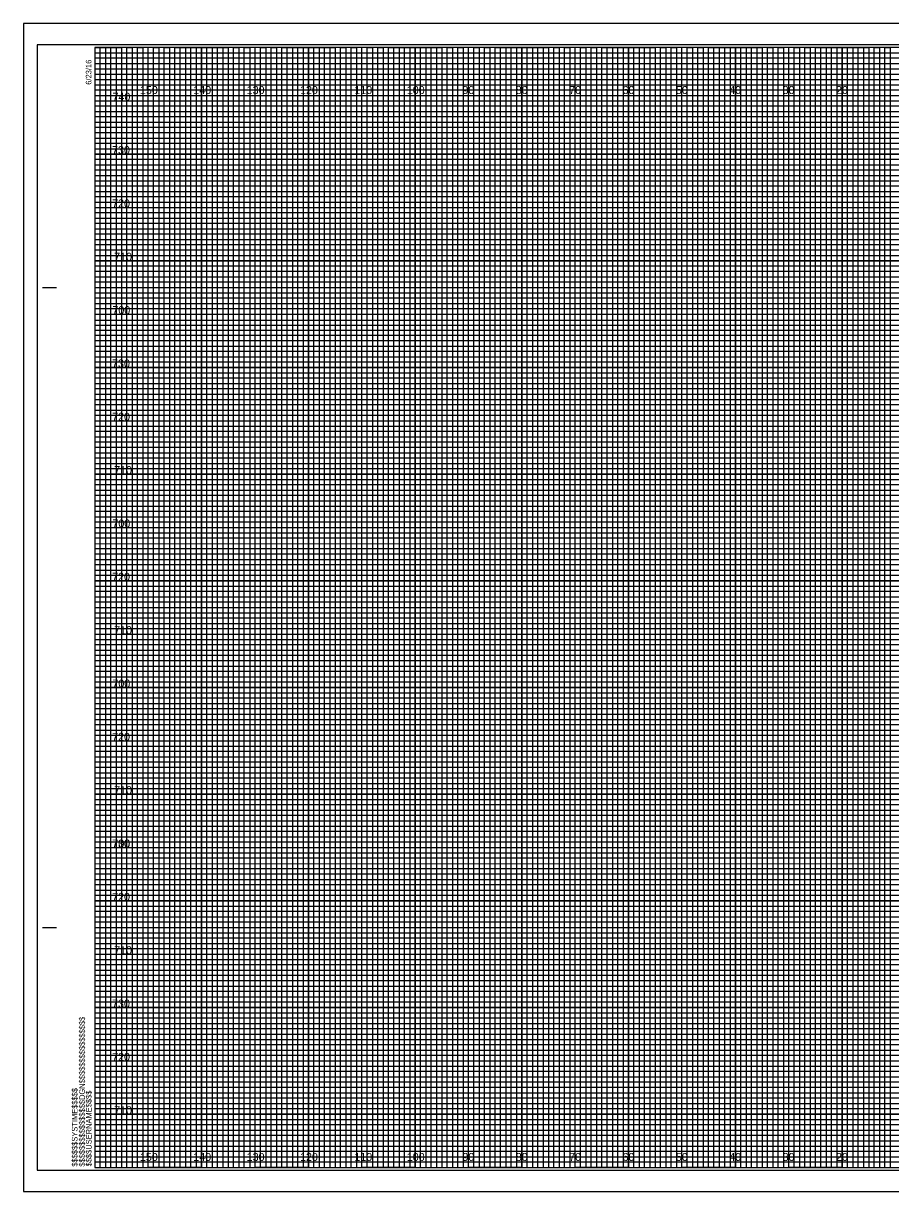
# Model space of a CAD drawing. Extents: x -13 to 323, y -4 to 434.
# Drawn here: x -13.4 to 149.1, y -4.5 to 214.5 of the extents above; entities that cross this region are included whole.
import ezdxf

# ---------------------------------------------------------------- set-up
doc = ezdxf.new("R2010")
doc.units = 0
for name, color, linetype in [('Exist XS Center Line Elevation Label', 7, 'Continuous'), ('Prop CMT Conc Surface', 7, 'Continuous'), ('Prop CMT Concrete Structures', 7, 'Continuous'), ('Prop CMT Pvmt Course 1 CG', 7, 'Continuous'), ('Prop CMT Pvmt Course 2', 7, 'Continuous'), ('Prop CMT Pvmt Course 3', 7, 'Continuous'), ('Prop CMT Pvmt Surface', 7, 'Continuous'), ('Prop CMT Subgrade Earthwork', 7, 'Continuous'), ('Prop XS Earthwork Shape', 7, 'Continuous'), ('Prop XS Elevation Labels', 7, 'Continuous'), ('Typical Curb CELL', 7, 'Continuous')]:
    doc.layers.add(name, color=color, linetype=linetype)

msp = doc.modelspace()

# ---------------------------------------------------------------- linework, layer by layer
at = {"layer": 'Exist XS Center Line Elevation Label'}
for p, q in [((0, 209), (260, 209)), ((260, 207.98), (0, 207.98)), ((0, 207.98), (0, 207)), ((0, 207), (260, 207)), ((260, 205.89), (0, 205.89)), ((0, 205.89), (0, 204)), ((0, 204), (320, 204))]:
    msp.add_line(p, q, dxfattribs=at)
for points in [[(0, 203), (270, 203), (320, 203), (320, 202), (0, 202)], [(0, 201), (320, 201), (320, 199), (0, 199)], [(0, 198), (320, 198), (320, 197), (0, 196.98)], [(0, 196), (320, 196), (320, 194), (0, 194)], [(0, 193), (320, 193), (320, 192), (0, 192)], [(0, 191), (320, 191), (320, 189), (0, 189)], [(0, 188), (320, 188), (320, 187), (0, 187)], [(0, 186), (320, 186), (320, 184), (0, 184)], [(0, 183), (320, 183), (320, 182), (0, 182)], [(0, 181), (320, 181), (320, 179), (0, 179)], [(0, 178), (320, 178), (320, 177), (0, 177)], [(0, 176), (320, 176), (320, 173.95), (320, 173), (320, 172), (0, 172)], [(0, 174), (320, 174), (320, 173), (0, 173)], [(0, 171), (320, 171), (320, 169), (0, 169.03)], [(0, 169.03), (320, 169), (320, 168), (0, 168)], [(0, 167), (320, 167), (320, 166), (0, 166)], [(0, 164), (320, 164), (320, 163), (0, 163)], [(0, 162), (320, 162), (320, 161), (0, 161)], [(-0.07, 158.89), (320, 158.89), (320, 157.88), (-0.07, 157.88)], [(0, 157), (320, 157), (320, 156), (0, 156)], [(0, 154), (320, 154), (320, 153), (0, 153)], [(0, 152), (320, 152), (320, 151), (0, 151)], [(0, 149), (320, 149), (320, 148), (0, 148)], [(0, 147), (320, 147), (320, 146), (0, 146)], [(0, 144), (320, 144), (320, 143), (0, 143)], [(0, 142), (320, 142), (320, 141), (0, 141)], [(0, 139), (320, 139), (319.99, 137.98), (0, 138)], [(0, 137), (320, 137), (320, 136), (0, 136)], [(0, 134), (320, 134), (320, 133), (0, 133)], [(0, 132), (320, 132), (320, 131), (0, 131)], [(0, 129), (320, 129), (320, 128), (0, 128)], [(0, 127), (320, 127), (320, 126), (0, 126)], [(0, 124), (320, 124), (320, 123), (0, 123)], [(0, 122), (320, 122), (320, 121), (0, 121)], [(0, 119), (320, 119), (320, 118), (0, 118)], [(0, 116.99), (320.07, 116.91), (320, 116), (0, 116)], [(0, 114), (320, 114), (320, 113), (0, 113)], [(0, 112), (320, 112), (320, 111), (0, 111)], [(0, 109), (320, 109), (320, 108), (0, 108)], [(0, 107), (320, 107), (320, 106), (0, 106)], [(0, 104), (320, 104), (320, 103), (0, 103)], [(0, 102), (320, 102), (320, 101), (0, 101)], [(0, 99), (320, 99), (320, 98), (0, 98)], [(0, 97), (320, 97), (320, 96), (0, 96)], [(0, 94), (320, 94), (320, 93), (0, 93)], [(0, 92), (320, 92), (320, 91), (0, 91)], [(0, 89), (320, 89), (320, 88), (0, 88)], [(0, 87), (320, 87), (320, 86), (0, 86)], [(0, 84), (320, 84), (320, 83), (0, 83)], [(0, 82), (320, 82), (320, 81), (0, 81)], [(0, 79), (320, 79), (319.99, 77.98), (0, 78)], [(0, 77), (320, 77), (320, 76), (0, 76)], [(0, 74), (320, 74), (320, 73), (0, 73)], [(0, 72), (320, 72), (320, 71), (0, 71)], [(0, 69), (320, 69), (320, 68), (0, 68)], [(0, 67), (320, 67), (320, 66), (0, 66)], [(0, 64), (320, 64), (320, 63), (0, 63)], [(0, 62), (320, 62), (320, 61), (0, 61)], [(0, 59), (320, 59), (320, 58), (0, 58)], [(0, 56.99), (320.07, 56.91), (320, 56), (0, 56)], [(0, 54), (320, 54), (320, 53), (0, 53)], [(0, 52), (320, 52), (320, 51), (0, 51)], [(0, 49), (320, 49), (320, 48), (0, 48)], [(0, 47), (320, 47), (320, 46), (0, 46)], [(0, 44), (320, 44), (320, 43), (0, 43)], [(0, 42), (320, 42), (320, 41), (0, 41)], [(0, 39), (320, 39), (320, 38), (0, 38)], [(0, 37), (320, 37), (320, 36), (0, 36)], [(0, 34), (320, 34), (320, 33), (0, 33)], [(0, 32), (320, 32), (320, 31), (0, 31)], [(0, 29), (320, 29), (320, 28), (0, 28)], [(0, 27), (320, 27), (320, 26), (0, 26)], [(0, 24), (320, 24), (320, 23), (0, 23)], [(0, 22), (320, 22), (320, 21), (0, 21)], [(0, 19), (320, 19), (320, 18), (0, 18)], [(0, 17), (320, 17), (320, 16), (0, 16)], [(0, 14), (320, 14), (320, 13), (0, 13)], [(0, 12), (320, 12), (320, 11), (0, 11)], [(0, 9), (320, 9), (320, 8), (0, 8)], [(0, 7), (320, 7), (320, 6), (0, 6)], [(0, 4), (320, 4), (320, 3), (0, 3)], [(0, 2), (320, 2), (320, 1), (0, 1)]]:
    msp.add_lwpolyline(points, dxfattribs=at)
at = {"layer": 'Prop CMT Conc Surface'}
for p, q in [((-9.8, 165), (-7.3, 165)), ((-9.7, 165), (-7.2, 165)), ((-9.8, 45), (-7.3, 45)), ((-9.7, 45), (-7.2, 45)), ((0, 0), (0, 0)), ((0, 0), (0, 0)), ((0, 0), (0, 0)), ((0, 0), (0, 0)), ((0, 0), (0, 0)), ((0, 0), (0, 0)), ((0, 0), (0, 0))]:
    msp.add_line(p, q, dxfattribs=at)
msp.add_lwpolyline([(320, 210), (0, 210), (0, 0), (320, 0)], close=True, dxfattribs=at)
at = {"layer": 'Prop CMT Concrete Structures'}
for p, q in [((10, 0), (10, 210)), ((20, 0), (20, 210)), ((30, 0), (30, 210)), ((40, 0), (40, 210)), ((50, 0), (50, 210)), ((60, 0), (60, 210)), ((70, 0), (70, 210)), ((80, 0), (80, 210)), ((90, 0), (90, 210)), ((100, 0), (100, 210)), ((110, 0), (110, 210)), ((120, 0), (120, 210)), ((130, 0), (130, 210)), ((140, 0), (140, 210)), ((0, 200), (320, 200)), ((0, 190), (320, 190)), ((0, 180), (320, 180)), ((0, 170), (320, 170)), ((0, 160), (320, 160)), ((0, 150), (320, 150)), ((0, 140), (320, 140)), ((0, 130), (320, 130)), ((0, 120), (320, 120)), ((0, 110), (320, 110)), ((0, 100), (320, 100)), ((0, 90), (320, 90)), ((0, 80), (320, 80)), ((0, 70), (320, 70)), ((0, 60), (320, 60)), ((0, 50), (320, 50)), ((0, 40), (320, 40)), ((0, 30), (320, 30)), ((0, 20), (320, 20)), ((0, 10), (320, 10))]:
    msp.add_line(p, q, dxfattribs=at)
at = {"layer": 'Prop CMT Pvmt Course 2'}
msp.add_lwpolyline([(-13.4, -4.5), (323.3, -4.5), (323.3, 214.5), (-13.4, 214.5)], close=True, dxfattribs=at)
at = {"layer": 'Prop CMT Pvmt Course 3'}
msp.add_lwpolyline([(-10.8, -0.5), (322.4, -0.5), (322.4, 210.5), (-10.8, 210.5)], close=True, dxfattribs=at)
at = {"layer": 'Prop CMT Pvmt Surface'}
for p, q in [((323.3, 214.5), (-13.4, 214.5)), ((-13.4, 214.5), (-13.4, -4.5)), ((-13.4, -4.5), (323.3, -4.5))]:
    msp.add_line(p, q, dxfattribs=at)
at = {"layer": 'Prop CMT Subgrade Earthwork'}
for points in [[(0, 0), (1, 0), (1, 210), (2, 210), (2, 0)], [(2, 0), (3, 0), (3, 210), (4, 210), (4, 0)], [(5, 0), (6, 0), (6, 210), (7, 210), (7, 0)], [(7, 0), (8, 0), (8, 210), (9, 210), (9, 0)], [(10, 0), (11, 0), (11, 210), (12, 210), (12, 0)], [(12, 0), (13, 0), (13, 210), (14, 210), (14, 0)], [(15, 0), (16, 0), (16, 210), (17, 210), (17, 0)], [(17, 0), (18, 0), (18, 210), (19, 210), (19, 0)], [(20, 0), (21, 0), (21, 210), (22, 210), (22, 0)], [(22, 0), (23, 0), (23, 210), (24, 210), (24, 0)], [(25, 0), (26, 0), (26, 210), (27, 210), (27, 0)], [(27, 0), (28, 0), (28, 210), (29, 210), (29, 0)], [(30, 0), (31, 0), (31, 210), (32, 210), (32, 0)], [(32, 0), (33, 0), (33, 210), (34, 210), (34, 0)], [(35, 0), (36, 0), (36, 210), (37, 210), (37, 0)], [(37, 0), (38, 0), (38, 210), (39, 210), (39, 0)], [(40, 0), (41, 0), (41, 210), (42, 210), (42, 0)], [(42, 0), (43, 0), (43, 210), (44, 210), (44, 0)], [(45, 0), (46, 0), (46, 210), (47, 210), (47, 0)], [(47, 0), (48, 0), (48, 210), (49, 210), (49, 0)], [(50, 0), (51, 0), (51, 210), (52, 210), (52, 0)], [(52, 0), (53, 0), (53, 210), (54, 210), (54, 0)], [(55, 0), (56, 0), (56, 210), (57, 210), (57, 0)], [(57, 0), (58, 0), (58, 210), (59, 210), (59, 0)], [(60, 0), (61, 0), (61, 210), (62, 210), (62, 0)], [(62, 0), (63, 0), (63, 210), (64, 210), (64, 0)], [(65, 0), (66, 0), (66, 210), (67, 210), (67, 0)], [(67, 0), (68, 0), (68, 210), (69, 210), (69, 0)], [(70, 0), (71, 0), (71, 210), (72, 210), (72, 0)], [(72, 0), (73, 0), (73, 210), (74, 210), (74, 0)], [(75, 0), (76, 0), (76, 210), (77, 210), (77, 0)], [(77, 0), (78, 0), (78, 210), (79, 210), (79, 0)], [(80, 0), (81, 0), (81, 210), (82, 210), (82, 0)], [(82, 0), (83, 0), (83, 210), (84, 210), (84, 0)], [(85, 0), (86, 0), (86, 210), (87, 210), (87, 0)], [(87, 0), (88, 0), (88, 210), (89, 210), (89, 0)], [(90, 0), (91, 0), (91, 210), (92, 210), (92, 0)], [(92, 0), (93, 0), (93, 210), (94, 210), (94, 0)], [(95, 0), (96, 0), (96, 210), (97, 210), (97, 0)], [(97, 0), (98, 0), (98, 210), (99, 210), (99, 0)], [(100, 0), (101, 0), (101, 210), (102, 210), (102, 0)], [(102, 0), (103, 0), (103, 210), (104, 210), (104, 0)], [(105, 0), (106, 0), (106, 210), (107, 210), (107, 0)], [(107, 0), (108, 0), (108, 210), (109, 210), (109, 0)], [(110, 0), (111, 0), (111, 210), (112, 210), (112, 0)], [(112, 0), (113, 0), (113, 210), (114, 210), (114, 0)], [(115, 0), (116, 0), (116, 210), (117, 210), (117, 0)], [(117, 0), (118, 0), (118, 210), (119, 210), (119, 0)], [(120, 0), (121, 0), (121, 210), (122, 210), (122, 0)], [(122, 0), (123, 0), (123, 210), (124, 210), (124, 0)], [(125, 0), (126, 0), (126, 210), (127, 210), (127, 0)], [(127, 0), (128, 0), (128, 210), (129, 210), (129, 0)], [(130, 0), (131, 0), (131, 210), (132, 210), (132, 0)], [(132, 0), (133, 0), (133, 210), (134, 210), (134, 0)], [(135, 0), (136, 0), (136, 210), (137, 210), (137, 0)], [(137, 0), (138, 0), (138, 210), (139, 210), (139, 0)], [(140, 0), (141, 0), (141, 210), (142, 210), (142, 0)], [(142, 0), (143, 0), (143, 210), (144, 210), (144, 0)], [(145, 0), (146, 0), (146, 210), (147, 210), (147, 0)], [(147, 0), (148, 0), (148, 210), (149, 210), (149, 0)]]:
    msp.add_lwpolyline(points, dxfattribs=at)
at = {"layer": 'Prop XS Elevation Labels'}
for p, q in [((10, 210), (0, 210)), ((10, 0), (10, 210)), ((30, 210), (20, 210)), ((20, 210), (20, 0)), ((30, 0), (30, 210)), ((50, 210), (40, 210)), ((40, 210), (40, 0)), ((50, 0), (50, 210)), ((70, 210), (60, 210)), ((60, 210), (60, 0)), ((70, 0), (70, 210)), ((90, 210), (80, 210)), ((80, 210), (80, 0)), ((90, 0), (90, 210)), ((110, 210), (100, 210)), ((100, 210), (100, 0)), ((110, 0), (110, 210)), ((130, 210), (120, 210)), ((120, 210), (120, 0)), ((130, 0), (130, 210)), ((150, 210), (140, 210)), ((140, 210), (140, 0)), ((20, 0), (10, 0)), ((40, 0), (30, 0)), ((60, 0), (50, 0)), ((80, 0), (70, 0)), ((100, 0), (90, 0)), ((120, 0), (110, 0)), ((140, 0), (130, 0))]:
    msp.add_line(p, q, dxfattribs=at)
for points in [[(0, 200), (320, 200), (320, 190), (0, 190)], [(0, 180), (320, 180), (320, 170), (0, 170)], [(0, 160), (320, 160), (320, 150), (0, 150)], [(0, 140), (320, 140), (320, 130), (0, 130)], [(0, 120), (320, 120), (320, 110), (0, 110)], [(0, 100), (320, 100), (320, 90), (0, 90)], [(0, 80), (320, 80), (320, 70), (0, 70)], [(0, 60), (320, 60), (320, 50), (0, 50)], [(0, 40), (320, 40), (320, 30), (0, 30)], [(0, 20), (320, 20), (320, 10), (0, 10)]]:
    msp.add_lwpolyline(points, dxfattribs=at)
at = {"layer": 'Typical Curb CELL'}
for points in [[(0, 210), (5, 210), (5, 0), (15, 0), (15, 210), (25, 210), (25, 0), (35, 0), (35, 210), (45, 210), (45, 0), (55, 0), (55, 210), (65, 210), (65, 0), (75, 0), (75, 210), (85, 210), (85, 0), (95, 0), (95, 210), (105, 210), (105, 0), (115, 0), (115, 210), (125, 210), (125, 0), (135, 0), (135, 210), (145, 210), (145, 0), (155, 0)], [(0, 205), (275, 205)], [(0, 185), (320, 185), (320, 195), (0, 195)], [(0, 165), (320, 165), (320, 175), (0, 175)], [(0, 145), (320, 145), (320, 155), (0, 155)], [(0, 125), (320, 125), (320, 135), (0, 135)], [(0, 105), (320, 105), (320, 115), (0, 115)], [(0, 85), (320, 85), (320, 95), (0, 95)], [(0, 65), (320, 65), (320, 75), (0, 75)], [(0, 45), (320, 45), (320, 55), (0, 55)], [(0, 25), (320, 25), (320, 35), (0, 35)], [(0, 5), (320, 5), (320, 15), (0, 15)]]:
    msp.add_lwpolyline(points, dxfattribs=at)

# ---------------------------------------------------------------- texts
at = {"layer": 'Prop CMT Conc Surface'}
for s, p in [('6/23/16', (-0.65, 203)), ('$$$$$$$$$$$$$$$$DGN$$$$$$$$$$$$$$$$', (-1.88, 0.18)), ('$$$$$$SYSTIME$$$$$', (-3.26, 0.18)), ('$$$$USERNAME$$$$', (-0.62, 0.23))]:
    msp.add_text(s, height=1.05, rotation=90, dxfattribs=at).set_placement(p)
at = {"layer": 'Prop CMT Pvmt Course 1 CG'}
for s, p in [('740', (3.3, 200)), ('730', (3.22, 190)), ('720', (3.23, 180)), ('710', (3.61, 170)), ('700', (3.28, 160)), ('730', (3.22, 150)), ('720', (3.23, 140)), ('710', (3.61, 130)), ('700', (3.28, 120)), ('720', (3.23, 110)), ('710', (3.61, 100)), ('700', (3.28, 90)), ('720', (3.23, 80)), ('710', (3.61, 70)), ('730', (3.22, 60)), ('700', (3.28, 60)), ('720', (3.23, 50)), ('710', (3.61, 40)), ('730', (3.22, 30)), ('720', (3.23, 20)), ('710', (3.61, 10))]:
    msp.add_text(s, height=1.5, dxfattribs=at).set_placement(p)
at = {"layer": 'Prop XS Earthwork Shape'}
for s, p in [('150', (8.44, 201.25)), ('140', (18.44, 201.25)), ('130', (28.44, 201.25)), ('120', (38.44, 201.25)), ('110', (48.62, 201.25)), ('100', (58.44, 201.25)), ('90', (68.86, 201.25)), ('80', (78.86, 201.25)), ('70', (88.86, 201.25)), ('60', (98.86, 201.25)), ('50', (108.86, 201.25)), ('40', (118.86, 201.25)), ('30', (128.86, 201.25)), ('20', (138.86, 201.25)), ('150', (8.44, 1.25)), ('140', (18.44, 1.25)), ('130', (28.44, 1.25)), ('120', (38.44, 1.25)), ('110', (48.62, 1.25)), ('100', (58.44, 1.25)), ('90', (68.86, 1.25)), ('80', (78.86, 1.25)), ('70', (88.86, 1.25)), ('60', (98.86, 1.25)), ('50', (108.86, 1.25)), ('40', (118.86, 1.25)), ('30', (128.86, 1.25)), ('20', (138.86, 1.25))]:
    msp.add_text(s, height=1.5, dxfattribs=at).set_placement(p)

doc.saveas('drawing.dxf')
